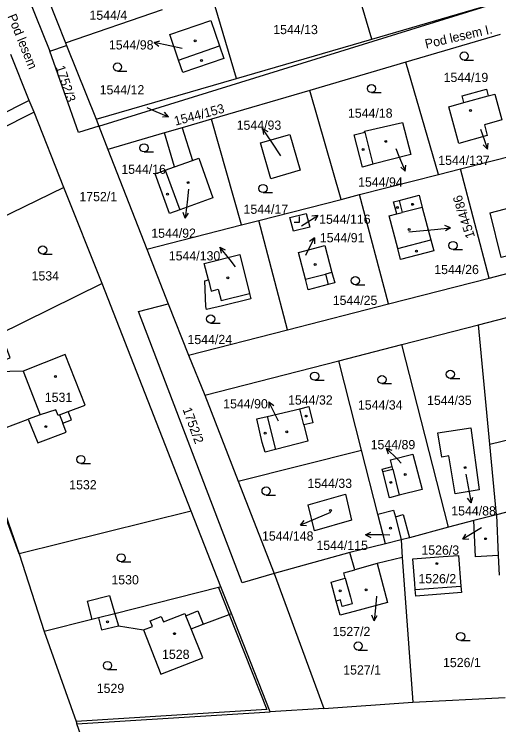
# Model space of a CAD drawing. Extents: x -724107 to -720612, y -1045267 to -1038441.
# Drawn here: x -722961.1 to -722871.9, y -1044252.9 to -1044121.9 of the extents above; entities that cross this region are included whole.
import ezdxf

# ---------------------------------------------------------------- set-up
doc = ezdxf.new("R2010")
doc.units = 0
for name, color, linetype in [('Hranice parcel', 7, 'Continuous'), ('Parcelní čísla', 7, 'Continuous'), ('Pop  PČ popisy', 7, 'Continuous'), ('Vnitřní kresba', 7, 'Continuous'), ('Značky budov', 7, 'Continuous'), ('Značky kultur', 7, 'Continuous')]:
    doc.layers.add(name, color=color, linetype=linetype)

msp = doc.modelspace()

# ---------------------------------------------------------------- linework, layer by layer
at = {"layer": 'Hranice parcel'}
for p, q in [((-722895.23, -1044126.49), (-722900.21, -1044109.63)), ((-722957.42, -1044112.75), (-722951.67, -1044127.16)), ((-722960.5, -1044113.9), (-722954.59, -1044128.74)), ((-722920.16, -1044133.74), (-722924.84, -1044118.02)), ((-722945.56, -1044142.52), (-722870.66, -1044119.34)), ((-722895.23, -1044126.49), (-722870.66, -1044119.34)), ((-722951.67, -1044127.16), (-722933.83, -1044121.04)), ((-722920.16, -1044133.74), (-722895.23, -1044126.49)), ((-722871.6, -1044125.66), (-722888.96, -1044130.74)), ((-722954.59, -1044128.74), (-722951.47, -1044127.66)), ((-722951.67, -1044127.16), (-722951.47, -1044127.66)), ((-722951.47, -1044127.66), (-722946.04, -1044141.27)), ((-722958.35, -1044137.78), (-722961.74, -1044129.33)), ((-722888.96, -1044130.74), (-722906.69, -1044135.94)), ((-722882.96, -1044151.44), (-722888.96, -1044130.74)), ((-722946.04, -1044141.27), (-722920.16, -1044133.74)), ((-722906.69, -1044135.94), (-722924.81, -1044141.25)), ((-722900.92, -1044156.02), (-722906.69, -1044135.94)), ((-722957.47, -1044139.98), (-722958.35, -1044137.78)), ((-722957.47, -1044139.98), (-722979.93, -1044151.09)), ((-722952.01, -1044153.85), (-722957.47, -1044139.98)), ((-722946.04, -1044141.27), (-722945.56, -1044142.52)), ((-722924.81, -1044141.25), (-722930.16, -1044142.86)), ((-722919.23, -1044160.73), (-722924.81, -1044141.25)), ((-722945.56, -1044142.52), (-722943.89, -1044146.83)), ((-722930.16, -1044142.86), (-722933.44, -1044143.77)), ((-722933.44, -1044143.77), (-722943.89, -1044146.83)), ((-722943.89, -1044146.83), (-722936.72, -1044165.22)), ((-722878.89, -1044150.39), (-722865.43, -1044146.94)), ((-722897.5, -1044155.14), (-722882.96, -1044151.44)), ((-722882.96, -1044151.44), (-722878.89, -1044150.39)), ((-722873.62, -1044170.52), (-722878.89, -1044150.39)), ((-722952.01, -1044153.85), (-722980.1, -1044167.58)), ((-722944.94, -1044171.56), (-722952.01, -1044153.85)), ((-722900.92, -1044156.02), (-722897.5, -1044155.14)), ((-722892.21, -1044175.29), (-722897.5, -1044155.14)), ((-722916.07, -1044159.92), (-722900.92, -1044156.02)), ((-722919.23, -1044160.73), (-722916.07, -1044159.92)), ((-722910.79, -1044180.06), (-722916.07, -1044159.92)), ((-722936.72, -1044165.22), (-722919.23, -1044160.73)), ((-722936.72, -1044165.22), (-722932.74, -1044175.27)), ((-722873.62, -1044170.52), (-722855.04, -1044165.75)), ((-722892.21, -1044175.29), (-722873.62, -1044170.52)), ((-722944.94, -1044171.56), (-722972.84, -1044185.26)), ((-722928.51, -1044213.47), (-722944.94, -1044171.56)), ((-722875.59, -1044179.16), (-722858.29, -1044174.66)), ((-722932.74, -1044175.27), (-722928.99, -1044184.73)), ((-722910.79, -1044180.06), (-722892.21, -1044175.29)), ((-722960.22, -1044221.34), (-722975.82, -1044180.11)), ((-722928.99, -1044184.73), (-722910.79, -1044180.06)), ((-722889.71, -1044182.79), (-722875.59, -1044179.16)), ((-722873.53, -1044201.14), (-722875.59, -1044179.16)), ((-722901.34, -1044185.77), (-722889.71, -1044182.79)), ((-722881.12, -1044216.47), (-722889.71, -1044182.79)), ((-722928.99, -1044184.73), (-722926.03, -1044192.12)), ((-722926.03, -1044192.12), (-722901.34, -1044185.77)), ((-722897.14, -1044202.24), (-722901.34, -1044185.77)), ((-722926.03, -1044192.12), (-722919.88, -1044207.95)), ((-722873.53, -1044201.14), (-722858.18, -1044197.3)), ((-722967.68, -1044200), (-722960.22, -1044221.34)), ((-722872.32, -1044214.15), (-722873.53, -1044201.14)), ((-722919.88, -1044207.95), (-722897.14, -1044202.24)), ((-722894.15, -1044214.02), (-722897.14, -1044202.24)), ((-722919.88, -1044207.95), (-722913.23, -1044224.96)), ((-722857.1, -1044210.3), (-722872.32, -1044214.15)), ((-722928.51, -1044213.47), (-722960.22, -1044221.34)), ((-722923.05, -1044227.43), (-722928.51, -1044213.47)), ((-722892.74, -1044219.54), (-722894.15, -1044214.02)), ((-722872.32, -1044214.15), (-722876.47, -1044215.2)), ((-722872.32, -1044214.15), (-722871.96, -1044221.68)), ((-722876.47, -1044215.2), (-722881.12, -1044216.47)), ((-722881.12, -1044216.47), (-722888.33, -1044218.38)), ((-722892.74, -1044219.54), (-722899.31, -1044221.14)), ((-722889.84, -1044218.78), (-722892.74, -1044219.54)), ((-722888.33, -1044218.38), (-722889.84, -1044218.78)), ((-722889.84, -1044218.78), (-722889.64, -1044222.02)), ((-722960.22, -1044221.34), (-722955.58, -1044235.7)), ((-722899.31, -1044221.14), (-722913.23, -1044224.96)), ((-722889.64, -1044222.02), (-722887.72, -1044248.72)), ((-722871.96, -1044221.68), (-722871.78, -1044225.3)), ((-722913.23, -1044224.96), (-722904.07, -1044249.89)), ((-722921.1, -1044232.36), (-722923.05, -1044227.43)), ((-722913.96, -1044250.46), (-722921.1, -1044232.36)), ((-722887.72, -1044248.72), (-722870.7, -1044247.86)), ((-722904.07, -1044249.89), (-722887.72, -1044248.72)), ((-722949.58, -1044252.69), (-722913.96, -1044250.46)), ((-722904.07, -1044249.89), (-722913.96, -1044250.46)), ((-722948.34, -1044256.18), (-722949.58, -1044252.69))]:
    msp.add_line(p, q, dxfattribs=at)
for points in [[(-722930.85, -1044130.35), (-722932.47, -1044125.63), (-722924.92, -1044123.04), (-722923.31, -1044127.73), (-722922.51, -1044130.07), (-722930.06, -1044132.66), (-722930.85, -1044130.35)], [(-722945.56, -1044142.52), (-722949.29, -1044143.68), (-722954.59, -1044128.74)], [(-722878.29, -1044138.19), (-722878.63, -1044136.92), (-722874.16, -1044135.69), (-722873.81, -1044136.97), (-722872.58, -1044136.63), (-722871.28, -1044141.39), (-722874.52, -1044142.27), (-722873.98, -1044144.28), (-722879.22, -1044145.71), (-722881.06, -1044138.95), (-722878.29, -1044138.19)], [(-722958.35, -1044137.78), (-722982.28, -1044149.85), (-722983.54, -1044147.54), (-722986.06, -1044142.19), (-722986.48, -1044141.33)], [(-722888.09, -1044147.78), (-722895.06, -1044149.56), (-722896.99, -1044150.06), (-722898.51, -1044144.11), (-722896.57, -1044143.65), (-722896.61, -1044143.48), (-722889.62, -1044141.83), (-722888.09, -1044147.78)], [(-722930.16, -1044142.86), (-722928.29, -1044148.88), (-722927.11, -1044148.46), (-722924.55, -1044155.75), (-722930.6, -1044157.96), (-722932.5, -1044158.65), (-722935.18, -1044151.3), (-722933.29, -1044150.64), (-722931.59, -1044150.04), (-722933.44, -1044143.77)], [(-722913.88, -1044152.21), (-722915.77, -1044145.61), (-722910.33, -1044144.04), (-722908.43, -1044150.64), (-722913.88, -1044152.21)], [(-722890.22, -1044156.24), (-722886.55, -1044155.28), (-722885.96, -1044157.5), (-722884.39, -1044163.47), (-722883.85, -1044165.5), (-722889.95, -1044167.11), (-722890.49, -1044165.08), (-722892.09, -1044159.07), (-722890.66, -1044158.69), (-722891.24, -1044156.51), (-722890.22, -1044156.24)], [(-722858.79, -1044163.5), (-722871.41, -1044166.74), (-722873.46, -1044158.48), (-722865.23, -1044156.35), (-722864.96, -1044157.34), (-722860.91, -1044156.32), (-722861.16, -1044155.35), (-722860.87, -1044155.29), (-722858.79, -1044163.5)], [(-722910.34, -1044159.37), (-722907.33, -1044158.6), (-722906.69, -1044161.12), (-722909.69, -1044161.89), (-722910.34, -1044159.37)], [(-722903.3, -1044171.72), (-722906.97, -1044172.68), (-722907.48, -1044170.75), (-722908.78, -1044165.81), (-722903.88, -1044164.53), (-722902.59, -1044169.48), (-722902.09, -1044171.4), (-722903.3, -1044171.72)], [(-722925.82, -1044175.79), (-722926, -1044171.06), (-722925.36, -1044170.84), (-722926.12, -1044167.83), (-722919.58, -1044166.17), (-722917.77, -1044173.37), (-722917.52, -1044174.34), (-722922.76, -1044175.63), (-722925.68, -1044176.35), (-722925.82, -1044175.79)], [(-722913.23, -1044224.96), (-722919.15, -1044226.68), (-722938.24, -1044176.68), (-722932.74, -1044175.27)], [(-722967.68, -1044200), (-722958.56, -1044196.52), (-722956.76, -1044200.9), (-722951.56, -1044198.95), (-722952.19, -1044197.26), (-722950.6, -1044196.67), (-722951.18, -1044195.12), (-722948.08, -1044193.95), (-722951.71, -1044184.64), (-722959.48, -1044187.67), (-722969.33, -1044187.96), (-722961.89, -1044185.23), (-722963.18, -1044181.72), (-722972.84, -1044185.26)], [(-722912.98, -1044202.1), (-722914.9, -1044202.59), (-722915.43, -1044200.85), (-722916.43, -1044196.49), (-722914.52, -1044196.04), (-722908.52, -1044194.61), (-722906.87, -1044194.22), (-722906.13, -1044197.21), (-722907.77, -1044197.61), (-722907.01, -1044200.6), (-722912.98, -1044202.1)], [(-722883.08, -1044199.06), (-722877.04, -1044198.13), (-722875.46, -1044209.54), (-722879.93, -1044210.28), (-722881.09, -1044203.31), (-722882.37, -1044203.52), (-722883.08, -1044199.06)], [(-722890.21, -1044210.56), (-722892.01, -1044211.02), (-722893.24, -1044206.21), (-722893.36, -1044205.73), (-722891.53, -1044205.27), (-722891.84, -1044204.04), (-722887.67, -1044202.96), (-722885.99, -1044209.48), (-722890.21, -1044210.56)], [(-722906.98, -1044212.35), (-722900.13, -1044210.38), (-722898.97, -1044215.14), (-722905.82, -1044217.11), (-722906.98, -1044212.35)], [(-722894.15, -1044214.02), (-722891.24, -1044213.28), (-722890.91, -1044214.51), (-722889.48, -1044214.12), (-722888.33, -1044218.38)], [(-722871.96, -1044221.68), (-722876.15, -1044221.89), (-722876.47, -1044215.2)], [(-722889.64, -1044222.02), (-722894.29, -1044223.12), (-722892.35, -1044230.33), (-722898.48, -1044231.98), (-722901.09, -1044232.68), (-722901.8, -1044230.07), (-722902.75, -1044226.55), (-722900.17, -1044225.86), (-722900.43, -1044224.88), (-722898.41, -1044224.33), (-722899.31, -1044221.14)], [(-722887.34, -1044226.85), (-722887.69, -1044222.29), (-722882.1, -1044221.86), (-722879.28, -1044221.64), (-722878.83, -1044227.3), (-722878.74, -1044228.5), (-722887.16, -1044229.15), (-722887.25, -1044227.96), (-722887.34, -1044226.85)], [(-722923.05, -1044227.43), (-722923.49, -1044227.54), (-722942.56, -1044232.41), (-722945.59, -1044233.18)], [(-722945.59, -1044233.18), (-722945.04, -1044235.39), (-722941.9, -1044234.62), (-722937.28, -1044235.37), (-722934.14, -1044243.54), (-722926.38, -1044240.5), (-722928.55, -1044235.21), (-722926.32, -1044234.29), (-722921.52, -1044232.52), (-722921.1, -1044232.36)], [(-722945.59, -1044233.18), (-722946.8, -1044233.49), (-722955.58, -1044235.7)], [(-722955.58, -1044235.7), (-722949.73, -1044252.27), (-722949.58, -1044252.69)]]:
    msp.add_lwpolyline(points, dxfattribs=at)
at = {"layer": 'Pop  PČ popisy'}
for p, q in [((-722935.36, -1044127.1), (-722934.28, -1044126.81)), ((-722932.43, -1044127.72), (-722935.36, -1044127.1)), ((-722935.36, -1044127.1), (-722934.49, -1044127.79)), ((-722930.2, -1044128.19), (-722932.43, -1044127.72)), ((-722936.72, -1044139.1), (-722935.46, -1044139.63)), ((-722935.46, -1044139.63), (-722932.7, -1044140.8)), ((-722932.7, -1044140.8), (-722933.82, -1044140.87)), ((-722932.7, -1044140.8), (-722933.42, -1044139.95)), ((-722913.68, -1044145.47), (-722915.36, -1044142.98)), ((-722915.36, -1044142.98), (-722914.38, -1044143.53)), ((-722915.36, -1044142.98), (-722915.21, -1044144.09)), ((-722875.26, -1044143.1), (-722874.95, -1044143.93)), ((-722874.95, -1044143.93), (-722873.92, -1044146.75)), ((-722911.99, -1044148.01), (-722913.68, -1044145.47)), ((-722873.92, -1044146.75), (-722874.74, -1044145.98)), ((-722873.92, -1044146.75), (-722873.8, -1044145.64)), ((-722890.86, -1044146.65), (-722890.26, -1044148.08)), ((-722890.26, -1044148.08), (-722889.09, -1044150.84)), ((-722889.09, -1044150.84), (-722889.94, -1044150.12)), ((-722889.09, -1044150.84), (-722889.02, -1044149.72)), ((-722929, -1044154.13), (-722929.29, -1044156.52)), ((-722929.29, -1044156.52), (-722929.66, -1044159.5)), ((-722929.66, -1044159.5), (-722930.03, -1044158.44)), ((-722929.66, -1044159.5), (-722929.04, -1044158.57)), ((-722907.72, -1044160.61), (-722905.18, -1044159.02)), ((-722905.18, -1044159.02), (-722906.29, -1044159.13)), ((-722905.18, -1044159.02), (-722905.76, -1044159.97)), ((-722908.21, -1044160.92), (-722907.72, -1044160.61)), ((-722888.46, -1044162.03), (-722883.73, -1044161.56)), ((-722883.73, -1044161.56), (-722880.74, -1044161.25)), ((-722880.74, -1044161.25), (-722881.79, -1044160.85)), ((-722880.74, -1044161.25), (-722881.69, -1044161.85)), ((-722907.18, -1044165.78), (-722905.82, -1044163.11)), ((-722905.82, -1044163.11), (-722906.72, -1044163.77)), ((-722905.82, -1044163.11), (-722905.83, -1044164.23)), ((-722921.37, -1044167.19), (-722923.26, -1044164.86)), ((-722923.26, -1044164.86), (-722922.24, -1044165.32)), ((-722923.26, -1044164.86), (-722923.02, -1044165.95)), ((-722907.43, -1044166.28), (-722907.18, -1044165.78)), ((-722920.36, -1044168.44), (-722921.37, -1044167.19)), ((-722914.2, -1044193.36), (-722914.21, -1044194.48)), ((-722912.88, -1044196.06), (-722914.2, -1044193.36)), ((-722914.2, -1044193.36), (-722913.31, -1044194.04)), ((-722912.46, -1044196.91), (-722912.88, -1044196.06)), ((-722890.48, -1044203.99), (-722892.6, -1044201.87)), ((-722892.6, -1044201.87), (-722891.54, -1044202.22)), ((-722892.6, -1044201.87), (-722892.25, -1044202.93)), ((-722889.83, -1044204.65), (-722890.48, -1044203.99)), ((-722877.95, -1044206.7), (-722877.51, -1044209.03)), ((-722877.51, -1044209.03), (-722876.94, -1044211.98)), ((-722876.94, -1044211.98), (-722877.62, -1044211.09)), ((-722876.94, -1044211.98), (-722876.64, -1044210.9)), ((-722902.86, -1044213.73), (-722905.65, -1044214.91)), ((-722905.65, -1044214.91), (-722908.41, -1044216.08)), ((-722908.41, -1044216.08), (-722907.69, -1044215.23)), ((-722908.41, -1044216.08), (-722907.3, -1044216.15)), ((-722875.06, -1044216.58), (-722875.95, -1044217.13)), ((-722896.43, -1044217.83), (-722895.42, -1044217.34)), ((-722893.43, -1044217.88), (-722896.43, -1044217.83)), ((-722896.43, -1044217.83), (-722895.44, -1044218.35)), ((-722891.96, -1044217.91), (-722893.43, -1044217.88)), ((-722875.95, -1044217.13), (-722878.52, -1044218.68)), ((-722878.52, -1044218.68), (-722877.92, -1044217.73)), ((-722878.52, -1044218.68), (-722877.41, -1044218.59)), ((-722894.37, -1044229.18), (-722894.54, -1044230.71)), ((-722894.54, -1044230.71), (-722894.85, -1044233.7)), ((-722894.85, -1044233.7), (-722895.25, -1044232.65)), ((-722894.85, -1044233.7), (-722894.25, -1044232.75))]:
    msp.add_line(p, q, dxfattribs=at)
at = {"layer": 'Vnitřní kresba'}
for p, q in [((-722930.85, -1044130.35), (-722923.31, -1044127.73)), ((-722878.29, -1044138.19), (-722873.81, -1044136.97)), ((-722896.57, -1044143.65), (-722895.06, -1044149.56)), ((-722931.59, -1044150.04), (-722928.29, -1044148.88)), ((-722933.29, -1044150.64), (-722930.6, -1044157.96)), ((-722890.22, -1044156.24), (-722889.64, -1044158.43)), ((-722885.96, -1044157.5), (-722889.64, -1044158.43)), ((-722890.66, -1044158.69), (-722889.64, -1044158.43)), ((-722890.49, -1044165.08), (-722884.39, -1044163.47)), ((-722907.48, -1044170.75), (-722903.8, -1044169.79)), ((-722902.59, -1044169.48), (-722903.8, -1044169.79)), ((-722903.8, -1044169.79), (-722903.3, -1044171.72)), ((-722925.36, -1044170.84), (-722924.84, -1044172.93)), ((-722924.84, -1044172.93), (-722923.53, -1044172.57)), ((-722923.53, -1044172.57), (-722923, -1044174.69)), ((-722923, -1044174.69), (-722917.77, -1044173.37)), ((-722959.48, -1044187.67), (-722956.36, -1044195.75)), ((-722907.77, -1044197.61), (-722908.52, -1044194.61)), ((-722956.36, -1044195.75), (-722958.56, -1044196.52)), ((-722953.44, -1044194.82), (-722956.36, -1044195.75)), ((-722953.03, -1044195.88), (-722953.44, -1044194.82)), ((-722952.77, -1044195.72), (-722953.03, -1044195.88)), ((-722952.77, -1044195.72), (-722951.18, -1044195.12)), ((-722952.77, -1044195.72), (-722952.19, -1044197.26)), ((-722914.52, -1044196.04), (-722912.98, -1044202.1)), ((-722893.24, -1044206.21), (-722891.41, -1044205.76)), ((-722891.41, -1044205.76), (-722891.53, -1044205.27)), ((-722891.41, -1044205.76), (-722890.21, -1044210.56)), ((-722890.91, -1044214.51), (-722889.84, -1044218.78)), ((-722894.29, -1044223.12), (-722898.41, -1044224.33)), ((-722900.17, -1044225.86), (-722899.19, -1044229.36)), ((-722887.25, -1044227.96), (-722878.83, -1044227.3)), ((-722923.49, -1044227.54), (-722921.52, -1044232.52)), ((-722947.68, -1044230.09), (-722943.56, -1044229.03)), ((-722943.56, -1044229.03), (-722942.56, -1044232.41)), ((-722901.03, -1044229.86), (-722901.8, -1044230.07)), ((-722900.7, -1044231.08), (-722901.03, -1044229.86)), ((-722899.19, -1044229.36), (-722898.85, -1044230.59)), ((-722947.68, -1044230.09), (-722946.8, -1044233.49)), ((-722898.85, -1044230.59), (-722900.7, -1044231.08)), ((-722942.56, -1044232.41), (-722941.9, -1044234.62)), ((-722933.63, -1044233.91), (-722929.72, -1044232.35)), ((-722929.72, -1044232.35), (-722929.54, -1044232.78)), ((-722929.54, -1044232.78), (-722927.3, -1044231.86)), ((-722927.3, -1044231.86), (-722926.32, -1044234.29)), ((-722921.52, -1044232.52), (-722914.58, -1044250.07)), ((-722936.05, -1044233.68), (-722934.04, -1044232.88)), ((-722935.64, -1044234.72), (-722936.05, -1044233.68)), ((-722934.04, -1044232.88), (-722933.63, -1044233.91)), ((-722928.55, -1044235.21), (-722929.54, -1044232.78)), ((-722937.28, -1044235.37), (-722935.64, -1044234.72)), ((-722914.58, -1044250.07), (-722949.73, -1044252.27))]:
    msp.add_line(p, q, dxfattribs=at)
at = {"layer": 'Značky budov'}
for centre in [(-722927.81, -1044126.82), (-722926.62, -1044130.43), (-722877.06, -1044139.64), (-722892.7, -1044145.33), (-722896.87, -1044146.84), (-722929.11, -1044152.94), (-722932.89, -1044155.06), (-722890.55, -1044157.54), (-722887.74, -1044156.94), (-722888.37, -1044161.6), (-722887.05, -1044165.59), (-722905.68, -1044168.05), (-722921.78, -1044170.47), (-722953.54, -1044188.69), (-722907.37, -1044195.96), (-722955.31, -1044197.91), (-722914.92, -1044199.13), (-722910.93, -1044198.86), (-722878.09, -1044205.47), (-722889.09, -1044206.75), (-722891.74, -1044208.18), (-722902.87, -1044213.36), (-722891.83, -1044216.61), (-722874.29, -1044218.57), (-722883.25, -1044223.16), (-722901.07, -1044228.17), (-722896.32, -1044227.98), (-722943.92, -1044233.88), (-722931.59, -1044236.07)]:
    msp.add_circle(centre, 0.175, dxfattribs=at)
at = {"layer": 'Značky kultur'}
for p, q in [((-722878.26, -1044130.34), (-722876.51, -1044130.34)), ((-722942.11, -1044132.39), (-722940.36, -1044132.39)), ((-722895.31, -1044136.35), (-722893.56, -1044136.35)), ((-722937.21, -1044147.28), (-722935.46, -1044147.28)), ((-722915.29, -1044154.77), (-722913.54, -1044154.77)), ((-722908.56, -1044160.21), (-722908.56, -1044159.21)), ((-722909.56, -1044160.21), (-722908.56, -1044160.21)), ((-722880.3, -1044165.27), (-722878.55, -1044165.27)), ((-722955.87, -1044166.1), (-722954.12, -1044166.1)), ((-722898.28, -1044171.75), (-722896.53, -1044171.75)), ((-722924.94, -1044178.82), (-722923.19, -1044178.82)), ((-722905.77, -1044189.36), (-722904.02, -1044189.36)), ((-722880.8, -1044189.02), (-722879.05, -1044189.02)), ((-722893.39, -1044189.99), (-722891.64, -1044189.99)), ((-722948.84, -1044204.72), (-722947.09, -1044204.72)), ((-722914.73, -1044210.52), (-722912.98, -1044210.52)), ((-722941.42, -1044222.83), (-722939.67, -1044222.83)), ((-722878.88, -1044237.35), (-722877.13, -1044237.35)), ((-722897.78, -1044239.09), (-722896.03, -1044239.09)), ((-722943.94, -1044242.69), (-722942.19, -1044242.69))]:
    msp.add_line(p, q, dxfattribs=at)
for centre in [(-722878.26, -1044129.59), (-722942.11, -1044131.64), (-722895.31, -1044135.6), (-722937.21, -1044146.53), (-722915.29, -1044154.02), (-722880.3, -1044164.52), (-722955.87, -1044165.35), (-722898.28, -1044171), (-722924.94, -1044178.07), (-722905.77, -1044188.61), (-722880.8, -1044188.27), (-722893.39, -1044189.24), (-722948.84, -1044203.97), (-722914.73, -1044209.77), (-722941.42, -1044222.08), (-722878.88, -1044236.6), (-722897.78, -1044238.34), (-722943.94, -1044241.94)]:
    msp.add_circle(centre, 0.75, dxfattribs=at)

# ---------------------------------------------------------------- texts
at = {"layer": 'Parcelní čísla'}
for s, p in [('1544/4', (-722947.26, -1044122.93)), ('1544/13', (-722913.41, -1044125.57)), ('1544/98', (-722943.68, -1044128.4)), ('1544/19', (-722882.03, -1044134.4)), ('1544/12', (-722945.38, -1044136.68)), ('1544/18', (-722899.65, -1044140.98)), ('1544/93', (-722920.15, -1044143.2)), ('1544/137', (-722883.02, -1044149.67)), ('1544/16', (-722941.39, -1044151.32)), ('1544/94', (-722897.78, -1044153.68)), ('1752/1', (-722949.12, -1044156.36)), ('1544/17', (-722918.88, -1044158.69)), ('1544/116', (-722904.96, -1044160.53)), ('1544/92', (-722935.87, -1044163.11)), ('1544/91', (-722904.83, -1044163.95)), ('1544/130', (-722932.65, -1044167.28)), ('1544/26', (-722883.75, -1044169.8)), ('1534', (-722957.92, -1044170.97)), ('1544/25', (-722902.45, -1044175.48)), ('1544/24', (-722929.21, -1044182.7)), ('1531', (-722955.49, -1044193.36)), ('1544/32', (-722910.68, -1044193.85)), ('1544/90', (-722922.63, -1044194.55)), ('1544/34', (-722897.81, -1044194.76)), ('1544/35', (-722885.08, -1044193.92)), ('1544/89', (-722895.47, -1044202.08)), ('1532', (-722950.99, -1044209.48)), ('1544/33', (-722907.11, -1044209.21)), ('1544/88', (-722880.62, -1044214.29)), ('1544/148', (-722915.48, -1044218.92)), ('1544/115', (-722905.46, -1044220.64)), ('1526/3', (-722886.12, -1044221.52)), ('1530', (-722943.22, -1044226.99)), ('1526/2', (-722886.67, -1044226.79)), ('1527/2', (-722902.48, -1044236.52)), ('1528', (-722933.89, -1044240.72)), ('1526/1', (-722882.14, -1044242.24)), ('1527/1', (-722900.52, -1044243.6)), ('1529', (-722945.92, -1044247))]:
    msp.add_text(s, height=1.7, dxfattribs=at).set_placement(p)
for s, rotation, p in [('1752/3', 288, (-722953.49, -1044131.64)), ('1544/153', 15, (-722931.42, -1044142.45)), ('1544/86', 108, (-722876.23, -1044162.9)), ('1752/2', 290, (-722930.14, -1044194.71))]:
    msp.add_text(s, height=1.7, rotation=rotation, dxfattribs=at).set_placement(p)
at = {"layer": 'Pop  PČ popisy'}
for s, rotation, p in [('Pod lesem', 292, (-722962.39, -1044122.25)), ('Pod lesem I.', 13, (-722885.25, -1044128.25))]:
    msp.add_text(s, height=1.7, rotation=rotation, dxfattribs=at).set_placement(p)

doc.saveas('drawing.dxf')
